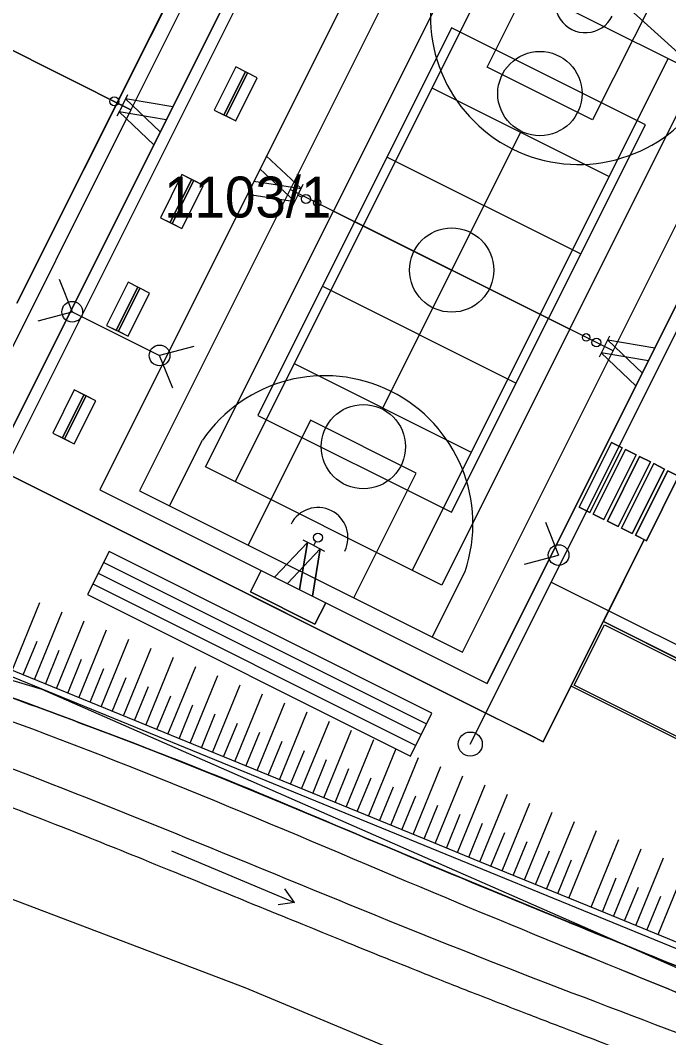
# Model space of a CAD drawing. Extents: x -504998 to -504814, y -1117353 to -1117234.
# Drawn here: x -504936.26 to -504909.32, y -1117323.49 to -1117281.23 of the extents above; entities that cross this region are included whole.
import ezdxf

# ---------------------------------------------------------------- set-up
doc = ezdxf.new("R2010")
doc.units = 0
for name, color, linetype in [('01_OPLOCENI', 7, 'Continuous'), ('01_ST tenká', 7, 'Continuous'), ('01_ST tlustá', 7, 'Continuous'), ('_01_CYKLOSTEZKA', 7, 'Continuous'), ('_01_kanalizace', 7, 'Continuous'), ('_01_pl', 7, 'Continuous'), ('_01_plachta', 7, 'Continuous'), ('_01_ST tenká', 7, 'Continuous'), ('_01_svah', 7, 'Continuous'), ('_01_VO', 7, 'Continuous'), ('_02_pl_ cesta', 7, 'Continuous'), ('Hranice parcel', 7, 'Continuous'), ('Parcelní čísla', 7, 'Continuous'), ('res_uzemi', 7, 'Continuous')]:
    doc.layers.add(name, color=color, linetype=linetype)

msp = doc.modelspace()

# ---------------------------------------------------------------- linework, layer by layer
at = {"layer": '01_OPLOCENI'}
msp.add_line((-504964.332, -1117297.166), (-504891.056, -1117327.134), dxfattribs=at)
at = {"layer": '01_ST tenká'}
for p, q in [((-504936.9, -1117298.759), (-504923.75, -1117272.464)), ((-504919.817, -1117274.431), (-504932.967, -1117300.726)), ((-504931.667, -1117284.941), (-504945.083, -1117278.232)), ((-504945.083, -1117278.232), (-504931.667, -1117284.941)), ((-504916.867, -1117308.777), (-504903.718, -1117282.482)), ((-504932.025, -1117284.762), (-504931.801, -1117284.315)), ((-504930.451, -1117285.863), (-504931.89, -1117284.494)), ((-504929.931, -1117284.823), (-504931.89, -1117284.494)), ((-504932.025, -1117284.762), (-504932.248, -1117285.209)), ((-504932.025, -1117284.762), (-504932.192, -1117284.678)), ((-504930.719, -1117286.4), (-504932.159, -1117285.03)), ((-504930.199, -1117285.36), (-504932.159, -1117285.03)), ((-504926.051, -1117286.86), (-504924.599, -1117288.216)), ((-504926.314, -1117287.399), (-504924.862, -1117288.755)), ((-504926.561, -1117287.905), (-504924.599, -1117288.216)), ((-504924.73, -1117288.486), (-504924.511, -1117288.036)), ((-504926.825, -1117288.444), (-504924.862, -1117288.755)), ((-504924.73, -1117288.486), (-504924.95, -1117288.935)), ((-504924.73, -1117288.486), (-504924.562, -1117288.568)), ((-504916.418, -1117310.259), (-504957.27, -1117289.83)), ((-504911.992, -1117294.78), (-504912.16, -1117294.696)), ((-504911.992, -1117294.78), (-504911.768, -1117294.332)), ((-504910.418, -1117295.881), (-504911.858, -1117294.511)), ((-504909.898, -1117294.841), (-504911.858, -1117294.511)), ((-504911.992, -1117294.78), (-504912.216, -1117295.227)), ((-504910.687, -1117296.418), (-504912.126, -1117295.048)), ((-504910.167, -1117295.378), (-504912.126, -1117295.048)), ((-504909.357, -1117299.938), (-504910.699, -1117302.621)), ((-504908.996, -1117300.118), (-504909.357, -1117299.938)), ((-504932.967, -1117300.726), (-504926.259, -1117304.081)), ((-504910.699, -1117302.621), (-504910.338, -1117302.802)), ((-504910.338, -1117302.802), (-504914.538, -1117311.2)), ((-504932.799, -1117303.745), (-504919.383, -1117310.454)), ((-504933.023, -1117304.192), (-504919.607, -1117310.901)), ((-504926.259, -1117304.081), (-504926.706, -1117304.975)), ((-504933.246, -1117304.639), (-504919.83, -1117311.348)), ((-504926.706, -1117304.975), (-504924.023, -1117306.317)), ((-504924.023, -1117306.317), (-504923.575, -1117305.423)), ((-504923.575, -1117305.423), (-504916.867, -1117308.777)), ((-504915.076, -1117310.93), (-504916.418, -1117310.259)), ((-504916.418, -1117310.259), (-504916.418, -1117310.259)), ((-504914.538, -1117311.2), (-504915.076, -1117310.93)), ((-504915.076, -1117310.93), (-504915.076, -1117310.93)), ((-504929.979, -1117315.734), (-504924.876, -1117317.87)), ((-504924.876, -1117317.87), (-504925.271, -1117317.315)), ((-504924.876, -1117317.87), (-504925.549, -1117317.978))]:
    msp.add_line(p, q, dxfattribs=at)
for points in [[(-504914.538, -1117311.2), (-504957.27, -1117289.83), (-504943.617, -1117262.53), (-504939.85, -1117264.413), (-504952.999, -1117290.709), (-504936.9, -1117298.759), (-504923.75, -1117272.464), (-504919.817, -1117274.431), (-504932.967, -1117300.726), (-504926.259, -1117304.081), (-504926.706, -1117304.975), (-504924.023, -1117306.317), (-504923.575, -1117305.423), (-504916.867, -1117308.777), (-504903.718, -1117282.482), (-504900.885, -1117283.898), (-504908.996, -1117300.118), (-504909.357, -1117299.938), (-504910.699, -1117302.621), (-504910.338, -1117302.802)], [(-504952.999, -1117290.709), (-504939.85, -1117264.413), (-504923.75, -1117272.464), (-504936.9, -1117298.759)], [(-504928.208, -1117284.956), (-504927.314, -1117285.403), (-504926.419, -1117283.615), (-504927.313, -1117283.167)], [(-504927.806, -1117285.157), (-504926.911, -1117283.369), (-504927.313, -1117283.167), (-504928.208, -1117284.956)], [(-504928.208, -1117284.956), (-504927.314, -1117285.403), (-504926.419, -1117283.615), (-504927.313, -1117283.167)], [(-504927.716, -1117285.202), (-504926.822, -1117283.413), (-504926.911, -1117283.369), (-504927.806, -1117285.157)], [(-504927.314, -1117285.403), (-504926.419, -1117283.615), (-504926.822, -1117283.413), (-504927.716, -1117285.202)], [(-504929.55, -1117289.875), (-504928.655, -1117288.087), (-504929.55, -1117287.639), (-504930.444, -1117289.428)], [(-504930.042, -1117289.629), (-504929.147, -1117287.841), (-504929.55, -1117287.639), (-504930.444, -1117289.428)], [(-504930.444, -1117289.428), (-504929.55, -1117289.875), (-504928.655, -1117288.087), (-504929.55, -1117287.639)], [(-504929.952, -1117289.674), (-504929.058, -1117287.885), (-504929.147, -1117287.841), (-504930.042, -1117289.629)], [(-504929.55, -1117289.875), (-504928.655, -1117288.087), (-504929.058, -1117287.885), (-504929.952, -1117289.674)], [(-504904.554, -1117291.237), (-504890.105, -1117298.46), (-504892.05, -1117302.352), (-504894.731, -1117301.011), (-504898.309, -1117308.166), (-504895.626, -1117309.508), (-504894.676, -1117307.607), (-504891.713, -1117309.091), (-504894.624, -1117314.913), (-504897.587, -1117313.429), (-504912.038, -1117306.206), (-504910.336, -1117302.802), (-504910.252, -1117302.845), (-504908.91, -1117300.161), (-504908.996, -1117300.118), (-504904.554, -1117291.235), (-504904.553, -1117291.235)], [(-504930.892, -1117292.559), (-504931.786, -1117292.111), (-504932.681, -1117293.9), (-504931.786, -1117294.347)], [(-504932.278, -1117294.101), (-504931.384, -1117292.313), (-504931.786, -1117292.111), (-504932.681, -1117293.9)], [(-504931.786, -1117294.347), (-504930.892, -1117292.559), (-504931.786, -1117292.111), (-504932.681, -1117293.9)], [(-504932.189, -1117294.146), (-504931.294, -1117292.357), (-504931.384, -1117292.313), (-504932.278, -1117294.101)], [(-504931.786, -1117294.347), (-504930.892, -1117292.559), (-504931.294, -1117292.357), (-504932.189, -1117294.146)], [(-504933.128, -1117297.031), (-504934.022, -1117296.583), (-504934.917, -1117298.372), (-504934.023, -1117298.819)], [(-504934.515, -1117298.573), (-504933.62, -1117296.785), (-504934.022, -1117296.583), (-504934.917, -1117298.372)], [(-504934.022, -1117296.583), (-504934.917, -1117298.372), (-504934.023, -1117298.819), (-504933.128, -1117297.031)], [(-504934.425, -1117298.618), (-504933.531, -1117296.829), (-504933.62, -1117296.785), (-504934.515, -1117298.573)], [(-504934.023, -1117298.819), (-504933.128, -1117297.031), (-504933.531, -1117296.829), (-504934.425, -1117298.618)], [(-504913.046, -1117301.449), (-504911.704, -1117298.766), (-504911.257, -1117298.989), (-504912.598, -1117301.673)], [(-504912.598, -1117301.673), (-504911.257, -1117298.989), (-504911.704, -1117298.766), (-504913.046, -1117301.449)], [(-504912.598, -1117301.673), (-504911.257, -1117298.989), (-504911.704, -1117298.766), (-504913.046, -1117301.449)], [(-504912.459, -1117301.742), (-504911.117, -1117299.059), (-504910.67, -1117299.282), (-504912.012, -1117301.966)], [(-504912.012, -1117301.966), (-504910.67, -1117299.282), (-504911.117, -1117299.059), (-504912.459, -1117301.742)], [(-504912.459, -1117301.742), (-504912.012, -1117301.966), (-504910.67, -1117299.282), (-504911.117, -1117299.059)], [(-504911.872, -1117302.035), (-504910.531, -1117299.352), (-504910.083, -1117299.575), (-504911.425, -1117302.259)], [(-504911.425, -1117302.259), (-504910.083, -1117299.575), (-504910.531, -1117299.352), (-504911.872, -1117302.035)], [(-504910.083, -1117299.575), (-504910.531, -1117299.352), (-504911.872, -1117302.035), (-504911.425, -1117302.259)], [(-504911.286, -1117302.328), (-504909.944, -1117299.645), (-504909.497, -1117299.868), (-504910.839, -1117302.552)], [(-504909.944, -1117299.645), (-504911.286, -1117302.328), (-504910.839, -1117302.552), (-504909.497, -1117299.868)], [(-504909.944, -1117299.645), (-504911.286, -1117302.328), (-504910.839, -1117302.552), (-504909.497, -1117299.868)], [(-504910.699, -1117302.621), (-504909.357, -1117299.938), (-504908.91, -1117300.161), (-504910.252, -1117302.845)], [(-504933.47, -1117305.086), (-504920.054, -1117311.795), (-504919.159, -1117310.007), (-504932.575, -1117303.298)]]:
    msp.add_lwpolyline(points, close=True, dxfattribs=at)
for points in [[(-504945.083, -1117278.232), (-504938.821, -1117265.71), (-504925.405, -1117272.419), (-504931.667, -1117284.941)], [(-504931.667, -1117284.941), (-504937.929, -1117297.462), (-504951.345, -1117290.753), (-504945.083, -1117278.232)], [(-504959.744, -1117288.593), (-504957.27, -1117289.83), (-504916.418, -1117310.259)], [(-504910.336, -1117302.802), (-504912.038, -1117306.206), (-504897.587, -1117313.429), (-504894.624, -1117314.913), (-504891.713, -1117309.091), (-504894.676, -1117307.607), (-504895.626, -1117309.508), (-504890.104, -1117298.458), (-504904.554, -1117291.235), (-504908.995, -1117300.119)], [(-504925.705, -1117304.358), (-504924.335, -1117302.918), (-504924.665, -1117304.878)], [(-504915.076, -1117310.93), (-504914.538, -1117311.2), (-504910.338, -1117302.802)], [(-504925.169, -1117304.626), (-504923.799, -1117303.187), (-504924.129, -1117305.146)]]:
    msp.add_lwpolyline(points, dxfattribs=at)
for centre in [(-504932.36, -1117284.594), (-504924.394, -1117288.65), (-504912.327, -1117294.612)]:
    msp.add_circle(centre, 0.185, dxfattribs=at)
for points in [[(-504979.676, -1117286.577), (-504975.526, -1117291.09), (-504971.924, -1117295.097), (-504967.609, -1117300.686), (-504961.055, -1117303.818), (-504949.588, -1117307.491), (-504933.661, -1117313.295), (-504916.676, -1117320.52), (-504900.945, -1117326.136), (-504889.034, -1117332.505), (-504883.929, -1117337.299), (-504881.859, -1117339.419)], [(-504980.257, -1117288.154), (-504977.765, -1117290.881), (-504976.785, -1117291.966), (-504974.842, -1117294.162), (-504973.881, -1117295.273), (-504972.466, -1117296.963), (-504971.765, -1117297.813), (-504971.076, -1117298.674), (-504970.619, -1117299.251), (-504970.394, -1117299.542), (-504969.896, -1117300.158), (-504969.627, -1117300.477), (-504969.169, -1117300.947), (-504969.007, -1117301.101), (-504968.678, -1117301.392), (-504968.51, -1117301.53), (-504967.657, -1117302.187), (-504966.932, -1117302.609), (-504965.846, -1117303.16), (-504965.484, -1117303.33), (-504964.768, -1117303.654), (-504964.416, -1117303.807), (-504963.358, -1117304.26), (-504962.653, -1117304.55), (-504959.129, -1117305.95), (-504956.315, -1117306.908), (-504952.123, -1117308.323), (-504950.732, -1117308.792), (-504947.95, -1117309.753), (-504943.777, -1117311.22), (-504939.618, -1117312.765), (-504934.102, -1117314.893), (-504931.361, -1117315.996), (-504925.877, -1117318.231), (-504923.135, -1117319.359), (-504918.999, -1117321.018), (-504917.616, -1117321.565), (-504914.845, -1117322.639), (-504913.46, -1117323.167), (-504909.316, -1117324.753), (-504906.566, -1117325.812), (-504902.501, -1117327.514), (-504901.156, -1117328.1), (-504898.491, -1117329.327), (-504897.173, -1117329.968), (-504894.596, -1117331.324), (-504893.337, -1117332.04), (-504890.908, -1117333.571), (-504889.742, -1117334.385), (-504887.004, -1117336.533), (-504885.468, -1117337.937), (-504883.972, -1117339.419)]]:
    msp.add_open_spline(points, degree=3, dxfattribs=at)
at = {"layer": '01_ST tlustá'}
msp.add_lwpolyline([(-504912.038, -1117306.206), (-504904.883, -1117309.784), (-504906.224, -1117312.467), (-504913.379, -1117308.889)], close=True, dxfattribs=at)
at = {"layer": '_01_CYKLOSTEZKA'}
for points in [[(-504978.999, -1117285.017), (-504976.7, -1117287.423), (-504974.687, -1117289.528), (-504972.137, -1117292.133), (-504971.625, -1117292.653), (-504970.597, -1117293.689), (-504970.083, -1117294.207), (-504969.05, -1117295.208), (-504968.53, -1117295.693), (-504967.466, -1117296.609), (-504966.923, -1117297.036), (-504964.081, -1117299.049), (-504961.455, -1117300.27), (-504956.072, -1117302.531), (-504953.347, -1117303.554), (-504945.119, -1117306.481), (-504939.563, -1117308.242), (-504928.573, -1117312.35), (-504923.185, -1117314.677), (-504915.108, -1117318.039), (-504912.41, -1117319.13), (-504907.001, -1117321.329), (-504904.293, -1117322.438), (-504900.239, -1117324.181), (-504898.887, -1117324.773), (-504896.196, -1117326.017), (-504894.86, -1117326.669), (-504892.238, -1117328.076), (-504890.953, -1117328.83), (-504888.469, -1117330.483), (-504887.279, -1117331.383), (-504883.84, -1117334.217), (-504881.711, -1117336.288), (-504879.247, -1117338.705), (-504878.883, -1117339.062), (-504878.518, -1117339.419)], [(-504979.438, -1117286.005), (-504976.794, -1117288.771), (-504973.013, -1117292.727), (-504966.78, -1117298.878), (-504954.231, -1117304.806), (-504936.613, -1117309.9), (-504917.359, -1117318.312), (-504902.231, -1117324.234), (-504889.176, -1117330.36), (-504883.067, -1117336.358), (-504879.947, -1117339.419)]]:
    msp.add_open_spline(points, degree=3, dxfattribs=at)
at = {"layer": '_01_kanalizace'}
msp.add_lwpolyline([(-504946.836, -1117237.019), (-504933.671, -1117256.588), (-504926.695, -1117266.535), (-504900.105, -1117290.54), (-504870.414, -1117320.168), (-504858.46, -1117339.419)], dxfattribs=at)
msp.add_lwpolyline([(-504946.836, -1117237.019), (-504933.671, -1117256.588), (-504926.695, -1117266.535), (-504900.105, -1117290.54), (-504870.414, -1117320.168), (-504858.46, -1117339.419)], dxfattribs=at)
at = {"layer": '_01_pl'}
for points in [[(-504927.314, -1117285.403), (-504926.419, -1117283.615), (-504927.313, -1117283.167), (-504928.208, -1117284.956)], [(-504929.55, -1117289.875), (-504928.655, -1117288.087), (-504929.55, -1117287.639), (-504930.444, -1117289.428)], [(-504931.786, -1117294.347), (-504930.892, -1117292.559), (-504931.786, -1117292.111), (-504932.681, -1117293.9)], [(-504934.023, -1117298.819), (-504933.128, -1117297.031), (-504934.022, -1117296.583), (-504934.917, -1117298.372)]]:
    msp.add_lwpolyline(points, close=True, dxfattribs=at)
at = {"layer": '_01_plachta'}
msp.add_lwpolyline([(-504911.993, -1117306.34), (-504905.017, -1117309.828), (-504906.269, -1117312.333), (-504913.245, -1117308.844)], close=True, dxfattribs=at)
at = {"layer": '_01_ST tenká'}
for p, q in [((-504936.403, -1117292.981), (-504928.075, -1117276.328)), ((-504916.707, -1117279.134), (-504927.338, -1117300.394)), ((-504909.346, -1117282.815), (-504919.977, -1117304.075)), ((-504919.16, -1117284.039), (-504911.799, -1117287.72)), ((-504915.48, -1117285.88), (-504921.205, -1117297.328)), ((-504921.025, -1117286.908), (-504912.976, -1117290.934)), ((-504911.634, -1117294.959), (-504925.05, -1117288.25)), ((-504923.248, -1117289.151), (-504913.436, -1117294.057)), ((-504922.367, -1117289.591), (-504914.317, -1117293.617)), ((-504923.709, -1117292.275), (-504915.659, -1117296.3)), ((-504924.885, -1117295.488), (-504917.524, -1117299.169)), ((-504925.705, -1117304.358), (-504924.335, -1117302.918)), ((-504924.665, -1117304.878), (-504924.335, -1117302.918)), ((-504924.067, -1117303.052), (-504924.514, -1117302.829)), ((-504924.067, -1117303.052), (-504923.983, -1117302.885)), ((-504924.067, -1117303.052), (-504923.62, -1117303.276)), ((-504925.169, -1117304.626), (-504923.799, -1117303.187)), ((-504924.129, -1117305.146), (-504923.799, -1117303.187)), ((-504919.148, -1117306.854), (-504917.784, -1117304.126))]:
    msp.add_line(p, q, dxfattribs=at)
for points in [[(-504919.817, -1117274.431), (-504932.967, -1117300.726), (-504916.867, -1117308.777), (-504903.718, -1117282.482)], [(-504918.788, -1117275.728), (-504931.312, -1117300.771), (-504917.896, -1117307.48), (-504905.372, -1117282.437)], [(-504908.121, -1117283.427), (-504918.752, -1117304.687), (-504928.564, -1117299.781), (-504917.932, -1117278.521)], [(-504918.342, -1117281.542), (-504926.392, -1117297.641), (-504918.343, -1117301.666), (-504910.292, -1117285.567)], [(-504923.575, -1117305.423), (-504924.023, -1117306.317), (-504926.706, -1117304.975), (-504926.259, -1117304.081)]]:
    msp.add_lwpolyline(points, close=True, dxfattribs=at)
for points in [[(-504928.075, -1117276.328), (-504936.403, -1117292.981)], [(-504909.889, -1117280.178), (-504909.889, -1117280.178), (-504912.483, -1117285.366), (-504916.866, -1117283.174), (-504914.272, -1117277.987)], [(-504922.413, -1117305.222), (-504922.413, -1117305.222), (-504919.818, -1117300.034), (-504924.201, -1117297.842), (-504926.795, -1117303.03)], [(-504930.06, -1117301.397), (-504930.06, -1117301.397), (-504928.696, -1117298.669)]]:
    msp.add_lwpolyline(points, dxfattribs=at)
for centre, radius in [((-504914.675, -1117284.27), 1.75), ((-504923.932, -1117288.809), 0.155), ((-504918.342, -1117291.604), 1.75), ((-504912.752, -1117294.4), 0.155), ((-504922.01, -1117298.938), 1.75), ((-504923.899, -1117302.717), 0.185)]:
    msp.add_circle(centre, radius, dxfattribs=at)
for centre, radius, start, end in [((-504913.068, -1117281.057), 6.158, 161.2907, 325.5723), ((-504912.785, -1117280.491), 1.25, 153.4315, 333.4315), ((-504923.616, -1117302.151), 6.158, 341.2907, 145.5723), ((-504923.899, -1117302.717), 1.25, 333.4315, 153.4315)]:
    msp.add_arc(centre, radius, start, end, dxfattribs=at)
at = {"layer": '_01_svah'}
for p, q in [((-504936.608, -1117308.234), (-504935.457, -1117305.42)), ((-504935.682, -1117308.613), (-504934.531, -1117305.798)), ((-504934.757, -1117308.991), (-504933.605, -1117306.177)), ((-504933.831, -1117309.37), (-504932.68, -1117306.555)), ((-504932.905, -1117309.748), (-504931.754, -1117306.934)), ((-504936.145, -1117308.423), (-504935.569, -1117307.016)), ((-504935.219, -1117308.802), (-504934.644, -1117307.395)), ((-504931.98, -1117310.127), (-504930.829, -1117307.312)), ((-504934.294, -1117309.181), (-504933.718, -1117307.773)), ((-504931.054, -1117310.505), (-504929.903, -1117307.691)), ((-504933.368, -1117309.559), (-504932.793, -1117308.152)), ((-504930.129, -1117310.884), (-504928.978, -1117308.069)), ((-504932.443, -1117309.938), (-504931.867, -1117308.53)), ((-504929.203, -1117311.263), (-504928.052, -1117308.448)), ((-504931.517, -1117310.316), (-504930.941, -1117308.909)), ((-504928.278, -1117311.641), (-504927.126, -1117308.827)), ((-504930.591, -1117310.695), (-504930.016, -1117309.287)), ((-504927.352, -1117312.02), (-504926.201, -1117309.205)), ((-504929.666, -1117311.073), (-504929.09, -1117309.666)), ((-504926.426, -1117312.398), (-504925.275, -1117309.584)), ((-504928.74, -1117311.452), (-504928.165, -1117310.045)), ((-504925.501, -1117312.777), (-504924.35, -1117309.962)), ((-504924.575, -1117313.155), (-504923.424, -1117310.341)), ((-504927.815, -1117311.83), (-504927.239, -1117310.423)), ((-504923.65, -1117313.534), (-504922.498, -1117310.719)), ((-504926.889, -1117312.209), (-504926.314, -1117310.802)), ((-504925.964, -1117312.588), (-504925.388, -1117311.18)), ((-504922.724, -1117313.912), (-504921.573, -1117311.098)), ((-504925.038, -1117312.966), (-504924.462, -1117311.559)), ((-504921.798, -1117314.291), (-504920.647, -1117311.476)), ((-504924.112, -1117313.345), (-504923.537, -1117311.937)), ((-504920.873, -1117314.67), (-504919.722, -1117311.855)), ((-504923.187, -1117313.723), (-504922.611, -1117312.316)), ((-504919.947, -1117315.048), (-504918.796, -1117312.233)), ((-504922.261, -1117314.102), (-504921.686, -1117312.694)), ((-504919.022, -1117315.427), (-504917.871, -1117312.612)), ((-504921.336, -1117314.48), (-504920.76, -1117313.073)), ((-504918.096, -1117315.805), (-504916.945, -1117312.991)), ((-504920.41, -1117314.859), (-504919.834, -1117313.451)), ((-504917.171, -1117316.184), (-504916.019, -1117313.369)), ((-504919.484, -1117315.237), (-504918.909, -1117313.83)), ((-504916.245, -1117316.562), (-504915.094, -1117313.748)), ((-504915.319, -1117316.941), (-504914.168, -1117314.126)), ((-504918.559, -1117315.616), (-504917.983, -1117314.209)), ((-504914.394, -1117317.319), (-504913.243, -1117314.505)), ((-504917.633, -1117315.994), (-504917.058, -1117314.587)), ((-504916.708, -1117316.373), (-504916.132, -1117314.966)), ((-504913.468, -1117317.698), (-504912.317, -1117314.883)), ((-504915.782, -1117316.752), (-504915.207, -1117315.344)), ((-504912.543, -1117318.076), (-504911.391, -1117315.262)), ((-504914.857, -1117317.13), (-504914.281, -1117315.723)), ((-504911.617, -1117318.455), (-504910.466, -1117315.64)), ((-504911.935, -1117318.325), (-504917.171, -1117316.184)), ((-504913.931, -1117317.509), (-504913.355, -1117316.101)), ((-504910.691, -1117318.834), (-504909.54, -1117316.019)), ((-504909.766, -1117319.212), (-504908.615, -1117316.397)), ((-504912.08, -1117318.266), (-504911.504, -1117316.858)), ((-504911.154, -1117318.644), (-504910.579, -1117317.237)), ((-504910.229, -1117319.023), (-504909.653, -1117317.616)), ((-504891.717, -1117326.594), (-504911.935, -1117318.325))]:
    msp.add_line(p, q, dxfattribs=at)
msp.add_lwpolyline([(-504917.171, -1117316.184), (-504919.484, -1117315.237), (-504964.237, -1117296.934)], dxfattribs=at)
at = {"layer": '_01_VO'}
for p, q in [((-504937.6, -1117301.277), (-504921.446, -1117268.973)), ((-504937.6, -1117301.277), (-504921.446, -1117268.973)), ((-504917.567, -1117311.295), (-504901.416, -1117278.997)), ((-504917.567, -1117311.295), (-504901.416, -1117278.997)), ((-504934.657, -1117291.976), (-504934.107, -1117293.336)), ((-504934.657, -1117291.976), (-504934.107, -1117293.336)), ((-504935.525, -1117293.711), (-504934.107, -1117293.336)), ((-504935.525, -1117293.711), (-504934.107, -1117293.336)), ((-504934.107, -1117293.336), (-504930.479, -1117295.15)), ((-504934.107, -1117293.336), (-504930.479, -1117295.15)), ((-504929.061, -1117294.775), (-504930.479, -1117295.15)), ((-504929.061, -1117294.775), (-504930.479, -1117295.15)), ((-504929.929, -1117296.51), (-504930.479, -1117295.15)), ((-504929.929, -1117296.51), (-504930.479, -1117295.15)), ((-504914.448, -1117302.082), (-504913.898, -1117303.442)), ((-504914.448, -1117302.082), (-504913.898, -1117303.442)), ((-504915.316, -1117303.817), (-504913.898, -1117303.442)), ((-504915.316, -1117303.817), (-504913.898, -1117303.442)), ((-504914.202, -1117304.565), (-504914.202, -1117304.565)), ((-504914.202, -1117304.565), (-504886.393, -1117318.466))]:
    msp.add_line(p, q, dxfattribs=at)
for centre, radius in [((-504934.107, -1117293.336), 0.43), ((-504934.107, -1117293.336), 0.43), ((-504930.479, -1117295.15), 0.43), ((-504930.479, -1117295.15), 0.43), ((-504913.898, -1117303.442), 0.43), ((-504913.898, -1117303.442), 0.43), ((-504917.567, -1117311.295), 0.5), ((-504917.567, -1117311.295), 0.5)]:
    msp.add_circle(centre, radius, dxfattribs=at)
at = {"layer": '_02_pl_ cesta'}
for points in [[(-504879.612, -1117338.347), (-504881.711, -1117336.288), (-504883.84, -1117334.217), (-504887.279, -1117331.383), (-504888.469, -1117330.483), (-504890.953, -1117328.83), (-504892.238, -1117328.076), (-504894.86, -1117326.669), (-504896.196, -1117326.017), (-504898.887, -1117324.773), (-504900.239, -1117324.181), (-504904.293, -1117322.438), (-504907.001, -1117321.329), (-504912.41, -1117319.13), (-504915.108, -1117318.039), (-504923.185, -1117314.677), (-504928.573, -1117312.35), (-504939.563, -1117308.242), (-504945.119, -1117306.481), (-504953.347, -1117303.554), (-504956.072, -1117302.531), (-504961.455, -1117300.27), (-504964.081, -1117299.049), (-504966.923, -1117297.036), (-504967.466, -1117296.609), (-504968.53, -1117295.693), (-504969.05, -1117295.208), (-504970.083, -1117294.207), (-504970.597, -1117293.689), (-504971.625, -1117292.653), (-504972.137, -1117292.133), (-504974.687, -1117289.528), (-504976.7, -1117287.423), (-504978.999, -1117285.017)], [(-504979.438, -1117286.005), (-504976.794, -1117288.771), (-504973.013, -1117292.727), (-504966.78, -1117298.878), (-504954.231, -1117304.806), (-504936.613, -1117309.9), (-504917.359, -1117318.312), (-504902.231, -1117324.234), (-504893.156, -1117328.493), (-504889.765, -1117330.828)]]:
    msp.add_open_spline(points, degree=3, dxfattribs=at)
at = {"layer": 'Hranice parcel'}
for points in [[(-504889.212, -1117339.419), (-504894.63, -1117334.91), (-504926.92, -1117321.42), (-504968.59, -1117305.61), (-504985.829, -1117285.298)], [(-504889.212, -1117339.419), (-504894.63, -1117334.91), (-504926.92, -1117321.42), (-504968.59, -1117305.61), (-504985.829, -1117285.298)], [(-504903.87, -1117322.84), (-504935.35, -1117309.03), (-504964.88, -1117300.19), (-504974.15, -1117290.02), (-504975.95, -1117287.76), (-504977.64, -1117285.4)]]:
    msp.add_lwpolyline(points, dxfattribs=at)
at = {"layer": 'res_uzemi'}
msp.add_lwpolyline([(-504906.832, -1117321.402), (-504910.082, -1117320.076), (-504912.108, -1117319.253), (-504914.011, -1117318.478), (-504919.244, -1117316.315), (-504925.453, -1117313.719), (-504927.742, -1117312.778), (-504931.511, -1117311.273), (-504936.157, -1117309.529), (-504942.139, -1117307.443), (-504949.128, -1117305.05), (-504951.334, -1117304.269), (-504953.633, -1117303.427), (-504955.171, -1117302.844), (-504957.115, -1117302.078)], dxfattribs=at)

# ---------------------------------------------------------------- texts
at = {"layer": 'Parcelní čísla'}
msp.add_text('1103/1', height=1.7, dxfattribs=at).set_placement((-504930.29, -1117289.42))

doc.saveas('drawing.dxf')
